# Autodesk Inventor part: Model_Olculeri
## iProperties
Company: Autodesk, Inc.
Shininess: 64.0
Length Units: 11269
Angle Units: 11279
Time Units: 11290
Mass Units: 11283
Length Display Precision: 3
Angle Display Precision: 2
Compacted: True
Part Number: Model_Olculeri
Document SubType Name: Modeling
Created: 2003-11
Catalog Web Link: www.autodesk.com
Vendor: Autodesk, Inc.
Designer: Administrator
Manufacturer: Standard
Standards Organization: Custom
Density: 1 g/cm^3
Density: 0.0
Volumn: 0.0
Area: 0.0
PropertySet Name: Model Information
Control State: 0
Master: False
Checked Out: False
Author: Administrator
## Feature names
1. Extrusion1
2. Extrusion2
3. Hole1
4. Extrusion3
5. Hole2
6. Hole3
7. Hole4
8. Hole5
9. Extrusion4
10. Chamfer1
